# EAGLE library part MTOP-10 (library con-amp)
AMP connector
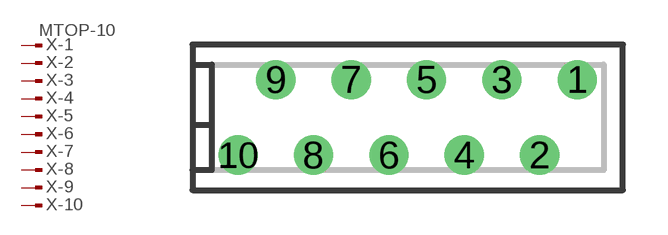
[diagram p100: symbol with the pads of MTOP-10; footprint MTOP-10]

Designator prefix X; gates -1=PIN-MV -2=PIN-M -3=PIN-M -4=PIN-M -5=PIN-M -6=PIN-M -7=PIN-M -8=PIN-M -9=PIN-M -10=PIN-M

## MTOP-10 (OC_FARNELL: unknown; OC_NEWARK: unknown)  [MTOP-10]
1  -1:1  pas
2  -2:1  pas
3  -3:1  pas
4  -4:1  pas
5  -5:1  pas
6  -6:1  pas
7  -7:1  pas
8  -8:1  pas
9  -9:1  pas
10  -10:1  pas

## Footprint MTOP-10 (pad centres in mm)
AMP connector
drill 0.813 round: 1 5.715,1.27; 2 4.445,-1.27; 3 3.175,1.27; 4 1.905,-1.27; 5 0.635,1.27; 6 -0.635,-1.27; 7 -1.905,1.27; 8 -3.175,-1.27; 9 -4.445,1.27; 10 -5.715,-1.27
